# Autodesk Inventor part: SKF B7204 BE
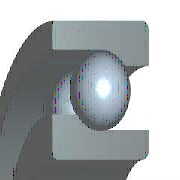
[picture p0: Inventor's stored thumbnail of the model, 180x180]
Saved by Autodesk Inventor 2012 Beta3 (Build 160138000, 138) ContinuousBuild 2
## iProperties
Created: 2010-11
Part Number: SKF B7204 BE
Material: Steel, Mild
Description: Single row angular contact ball bearings SKF
Document SubType Name: Modeling
Standard: SKF B
Designer: Beta-8540w
Language: en-US
Size Designation: SKF B7204 BE
Categories: <MemberInstance><Categories><Category DisplayName="Shaft Parts" InternalName="7f7aeb1f-a693-4053-b835-cee3144e0d98" Mnemonic="SHFT"><Category DisplayName="Beari
Density: 7.86 g/cm^3
IsCustomPart: 0
Author: Beta-8540w
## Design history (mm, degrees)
node "WorkPlane1"
workplane "Work Plane2"
node "WorkPlane2"
node "Sketch1"
node "WorkPoint1"
node "Sketch2"
node "WorkPoint3"
node "Sketch3"
node "WorkPoint2"
node "WorkAxis1"
node "Sketch7"
workaxis "Work Axis2"
pattern_circular "PolarArray1" dims angle "d18" = 360 deg
fillet "Fillet1" dims "d19" = 0.6 (= r1)
fillet "Fillet2" dims "d20" = 1 (= r)
body "Solid1"
revolve "Revolution1" stored, may be unused: angle "d7" = 360 deg
revolve "Revolution2" stored, may be unused: angle "d12" = 360 deg
revolve "Revolution3" stored, may be unused: angle "d15" = 360 deg
sketch "Sketch4"
  geometry: L1 (23.5, 0)-(10, 0); L2 (23.5, 14)-(23.5, 0); L3 (10, 14)-(23.5, 14); L4 (10, 0)-(10, 14); L5 (0, -3.737)-(0, 15.931); L6 (0, -3.737)-(0, 15.931); L7 (0, -7.671)-(0, 19.865) reference; L8 (-4.7, 0)-(28.2, 0) reference
  constraints: 12 end point, 3 vertical, 2 collinear, 2 horizontal
  dimensions: "d2" = 10 horizontal distance of L3.start L5.end (= 0.5 x Diam); "d4" = 23.5 horizontal distance of L2.start L5.end (= 0.5 x DD); "d6" = 14 distance of L1.end L3.start (= B)
sketch "Sketch5"
  geometry: L1 (20.8, 14)-(14.32, 14); L2 (20.8, 7)-(20.8, 14); L3 (19.18, 0)-(19.18, 3.76); L4 (12.7, 0)-(19.18, 0); L5 (12.7, 7)-(12.7, 0); L6 (14.32, 14)-(14.32, 10.24); L7 (23.5, 0)-(-23.5, 0) reference; L8 (23.5, 14)-(-23.5, 14) reference; L9 (0, 40.963)-(0, -26.963); L10 (0, -40.549)-(0, 54.549) reference; A1 r 4.05 centre (16.75, 7) between (19.18, 3.76) and (20.8, 7); A2 r 4.05 centre (16.75, 7) between (14.32, 10.24) and (12.7, 7); A3 r 4.05 centre (16.75, 7) between (20.8, 7) and (14.32, 10.24)
  constraints: 14 end point, 7 point on circle, 4 vertical, 3 centre point, 3 collinear, 2 horizontal, 2 tangent, 1 coincident, 1 concentric
  dimensions: "d9" = 7 vertical distance of A2.centre L3.start (= 0.5 x B); "d11" = 8.1 diameter of A3 (= msp_mdtdk); "d21" = 33.5 diameter of A1.centre L9 (= msp_mdtds); "d22" = 28.64 diameter of L6 L9 (= msp_md); "d23" = 38.36 diameter of L3 L9 (= msp_vd)
sketch "Sketch6"
  geometry: L1 (16.75, 2.95)-(16.75, 11.05); L2 (16.75, 15.175)-(16.75, -1.013); L3 (23.5, 0)-(-23.5, 0) reference; L4 (16.75, 15.175)-(16.75, -1.013); L5 (20.8, 7)-(-20.8, 7) reference; A1 r 4.05 centre (16.75, 7) between (16.75, 2.95) and (16.75, 11.05); A2 r 4.05 centre (16.75, 7) between (14.32, 10.24) and (12.7, 7) reference
  constraints: 6 end point, 4 point on line, 2 point on circle, 1 centre point, 1 concentric, 1 vertical
  dimensions: "d14" = 4.05 radius of A1 (= 0.5 x msp_mdtdk)
other parameters: "DD" = 47 [user parameter; used in 3 equation terms], "B" = 14 [user parameter; used in 3 equation terms], "r" = 1 [user parameter; used in 1 equation term], "msp_mdtdk" = 8.1 (= -0.3 x Diam + 0.3 x DD) [user parameter; used in 5 equation terms], "msp_mdtds" = 33.5 (= 0.5 x DD + 0.5 x Diam) [user parameter; used in 4 equation terms], "msp_md" = 28.64 (= msp_mdtds - 0.6 x msp_mdtdk) [user parameter; used in 1 equation term], "msp_vd" = 38.36 (= msp_mdtds + 0.6 x msp_mdtdk) [user parameter; used in 1 equation term], "r1" = 0.6 [user parameter; used in 1 equation term], "d0" = -14 (computed from B), "d3" = 23.5 (derived), "d5" = 14 (derived), "d8" = 7 (derived), "d10" = 8.1 (derived), "d13" = 4.05 (derived), "d26" = 0, "d27" = 0, "d28" = 0, "d29" = 0, "d30" = 0
